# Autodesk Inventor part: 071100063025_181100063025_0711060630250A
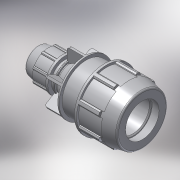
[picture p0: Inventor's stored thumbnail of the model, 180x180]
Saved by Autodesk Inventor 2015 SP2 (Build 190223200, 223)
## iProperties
Created: 2017-02
Part Number: 071100063025_181100063025_0711060630250A
Material: PVC-Piping
Description: PLASSON REDUCING COUPLER 63-25
Document SubType Name: Modeling
Designer: KIM
Mass: 92.6774 g
Surface Area: 199.44 cm^2
Volume: 66.1981 cm^3
Density: 1.4 g/cm^3
Appearance: Smooth - White
Author: KIM
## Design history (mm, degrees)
derived "07110.ipt"
feature "Solid1::07110.ipt"
tag "TaggingFeature1"
body "Solid1"
other parameters: "d2" = 63, "d4" = 16.08333, "d5" = 27.57143, "d7" = 113, "d9" = 27.57143, "d11" = 2.75714, "d12" = 90.4, "d13" = 120 deg, "d14" = 94.5, "d15" = 12 deg, "d16" = 101.7, "d18" = 3.15, "d19" = 35 deg, "d20" = 17.5 deg, "d21" = 105.09, "d23" = 0, "d25" = 360 deg, "d27" = 2.26, "d42" = 42.46, "d46" = 1.89, "d51" = 193, "d52" = 27.57143, "d53" = 12 deg, "d56" = 37.5, "d57" = 25, "d58" = 56.7, "d59" = 22.5, "d60" = 48.6, "d61" = 43.2, "d62" = 19.3, "d63" = 30.88, "d64" = 120 deg, "d65" = 54, "d68" = 13.78571, "d74" = 50.22, "d75" = 35 deg, "d76" = 17.5 deg, "d78" = 0, "d80" = 360 deg, "d85" = 1.08, "d88" = 0.5, "d93" = 58, "d94" = 79.1, "d97" = 3.31667, "d98" = 3.6, "d99" = 0, "d100" = 4.52, "d102" = 360 deg, "d104" = 2, "d106" = 0, "d107" = 3.6, "d108" = 0, "d109" = 3.6, "d110" = 0, "d_" = 63, "E_" = 113, "H_" = 193, "d_1" = 25, "E_1" = 54, "l_1" = 58, "d96" = 9.95
